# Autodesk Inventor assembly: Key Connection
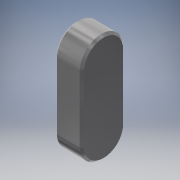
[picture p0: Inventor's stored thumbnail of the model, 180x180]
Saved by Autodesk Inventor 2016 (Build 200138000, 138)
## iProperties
ClientObjectVersion: 1
Created: 2015-08
Part Number: Key Connection
Document SubType Name: Assembly
Designer: Ugljesa
Mass: 5.68026 g
Surface Area: 5.14753 cm^2
Volume: 0.7236 cm^3
Density: 7.85 g/cm^3
Author: Ugljesa
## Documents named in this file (2)
- C:\Users\Ugljesa\Desktop\Turbokompr\Sklop turbokompresora\Design Accelerator\Key Connection4.iam
- C:\Users\Ugljesa\Documents\Inventor\Content Center Files\R2016\en-US\ISO 2491 - A\ISO 2491 - A  8 x 5 x 20.ipt
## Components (1 placed, 1 different names)
1. ISO 2491 A A  8 x 5 x 20:1
